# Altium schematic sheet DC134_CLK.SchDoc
size 431 x 279 mm; Date: Not shown in title block; ApprovedBy: Not shown in title block; CheckedBy: Not shown in title block; Author: Not shown in title block; CompanyName: Not shown in title block; Engineer: Not shown in title block; Organization: Not shown in title block; Address1: Not shown in title block; Address2: Not shown in title block; Address3: Not shown in title block; Address4: Not shown in title block; DocumentNumber: 4; Revision: Use project parameter SCH_Rev; SheetNumber: 4; SheetTotal: 9; PageSetup: Record=PageOptions¦CenterHorizontal=True¦CenterVertical=True¦PrintScale=1.00¦XCorrection=1.00¦YCorrection=1.00¦PrintKind=0¦BorderSize=5000000¦LeftOffset=0¦BottomOffset=0¦Orientation=2¦PaperLength=1000¦PaperWidth=1000¦Scale=100¦PaperSource=15¦PrintQuality=600¦MediaType=1¦DitherType=10¦PaperKind=Letter¦PrintScaleMode=1
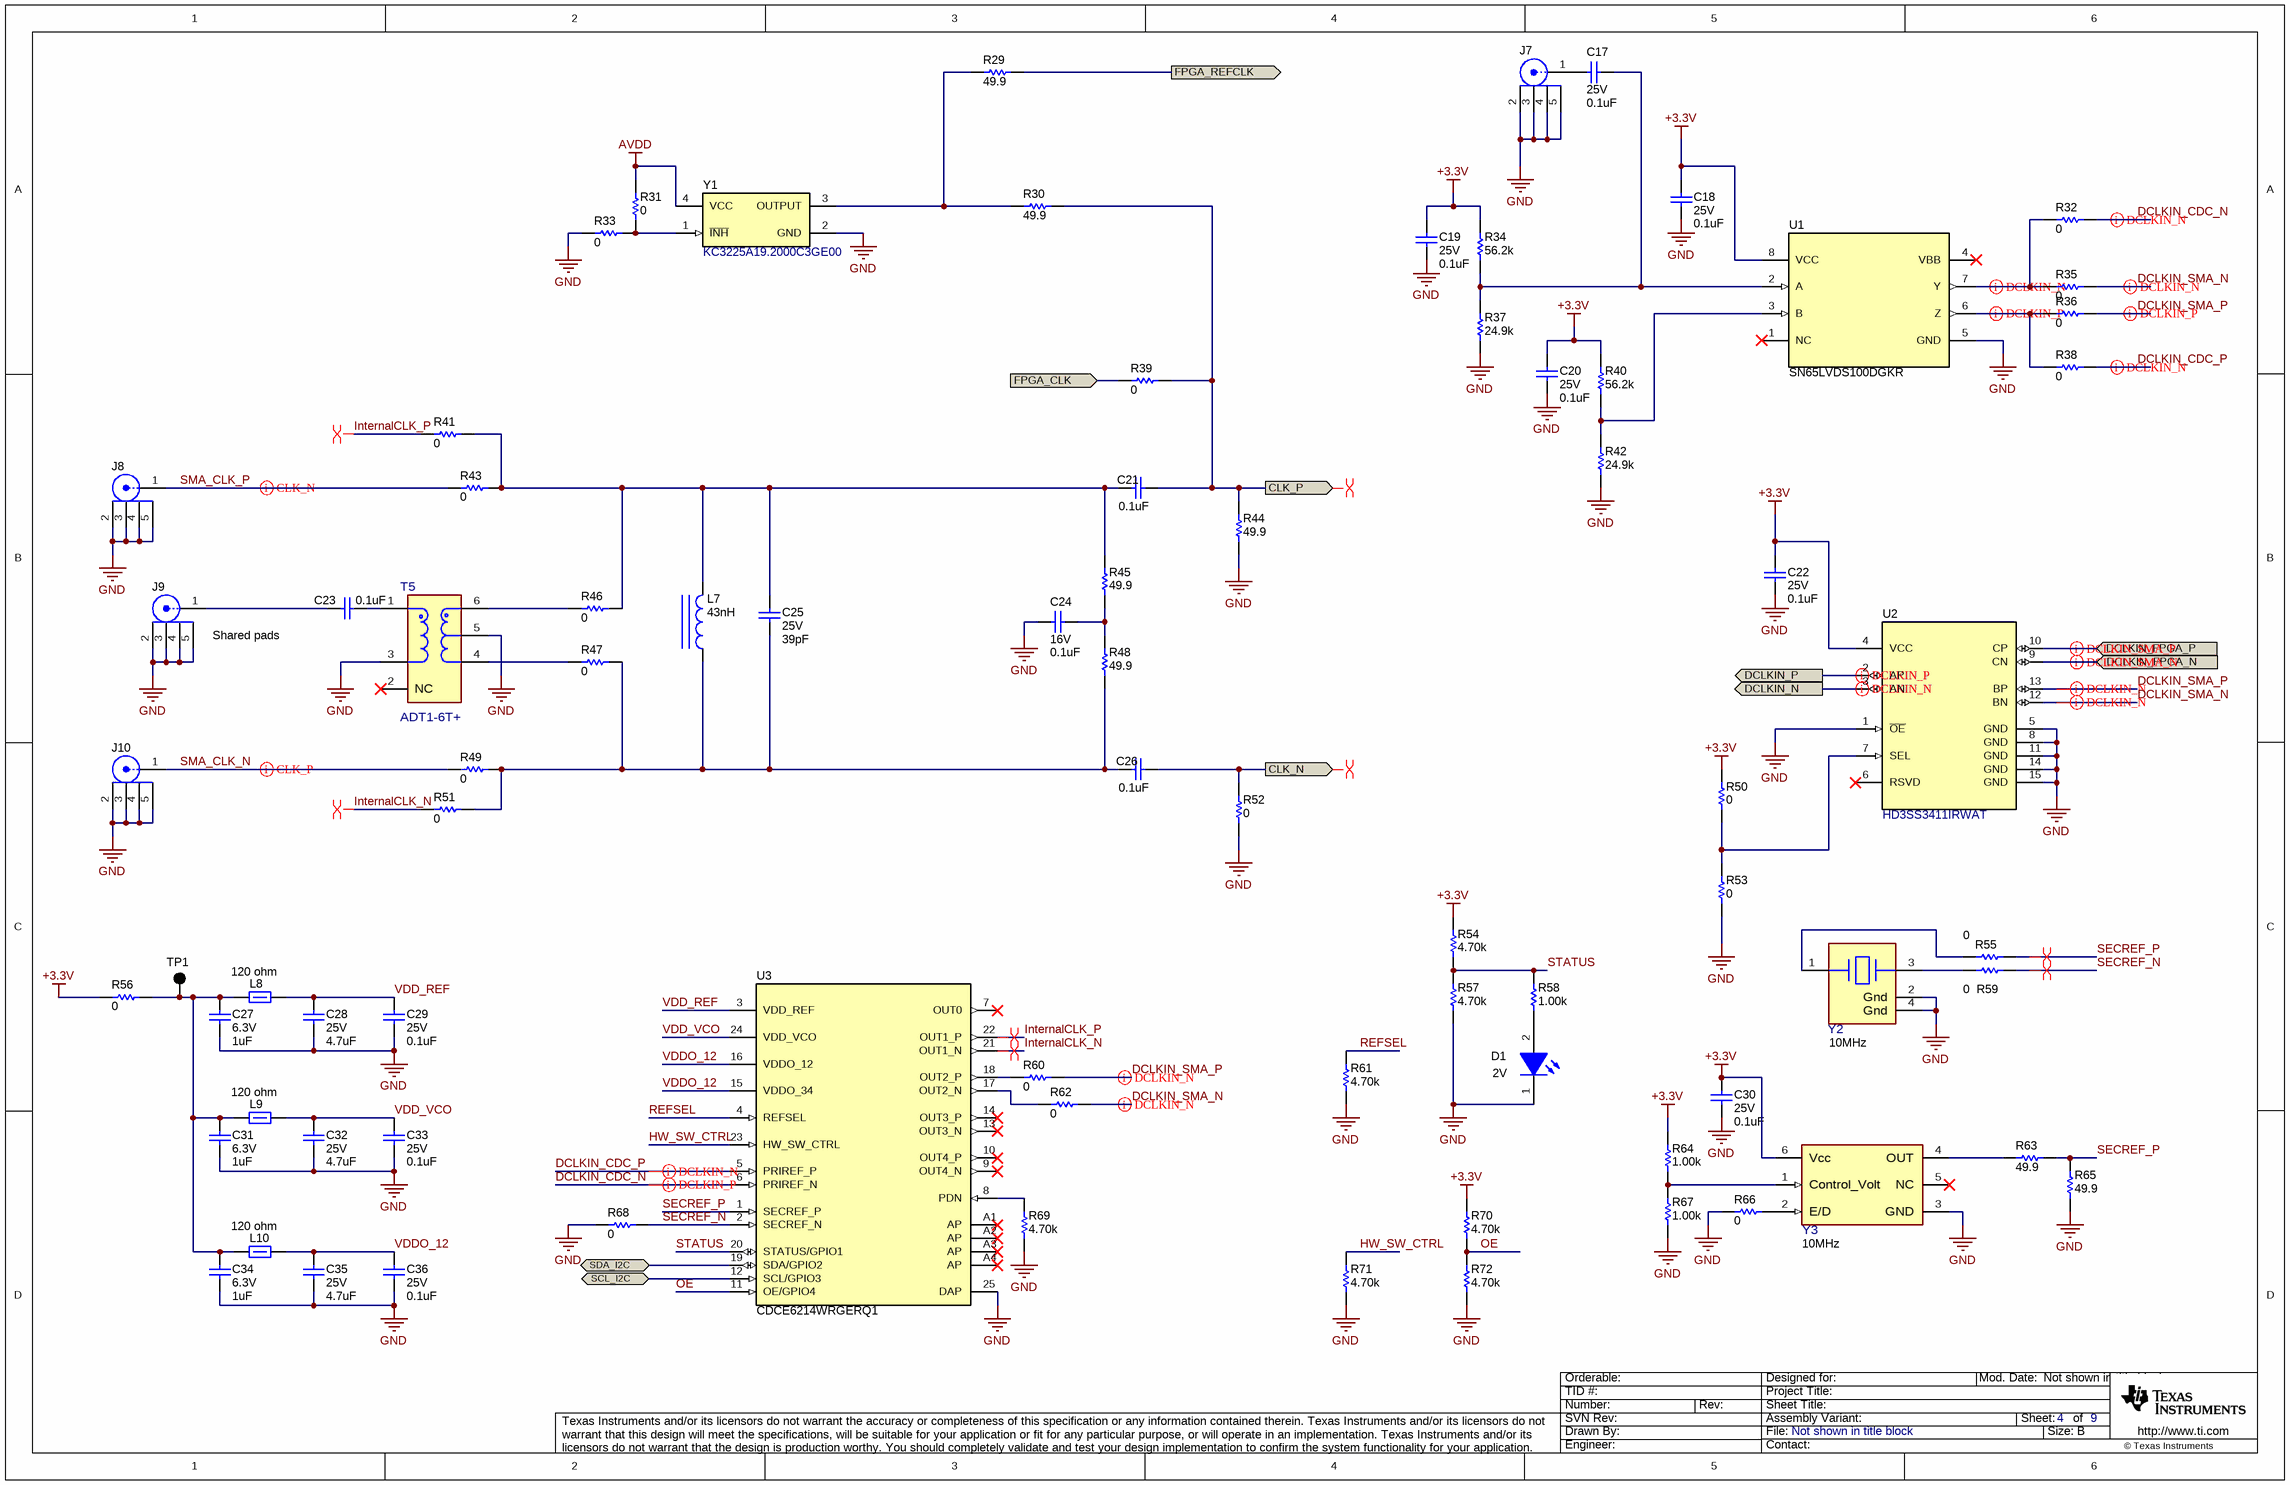
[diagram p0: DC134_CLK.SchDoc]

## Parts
C17  VDC_V: 25V  ValueDisplayed: 0.1uF  [0402]  (hidden comment: GRM155R61E104KA87D)
C18  VDC_V: 25V  ValueDisplayed: 0.1uF  [0402]  (hidden comment: GRM155R61E104KA87D)
C19  VDC_V: 25V  ValueDisplayed: 0.1uF  [0402]  (hidden comment: GRM155R61E104KA87D)
C20  VDC_V: 25V  ValueDisplayed: 0.1uF  [0402]  (hidden comment: GRM155R61E104KA87D)
C21  ValueDisplayed: 0.1uF  [0201L]  (hidden comment: GRM033Z71C104KE14D)
C22  VDC_V: 25V  ValueDisplayed: 0.1uF  [0402]  (hidden comment: GRM155R61E104KA87D)
C23  ValueDisplayed: 0.1uF  [0201L]  (hidden comment: GRM033Z71C104KE14D)
C24  VDC_V: 16V  ValueDisplayed: 0.1uF  [0201L]  (hidden comment: GRM033Z71C104KE14D)
C25  VDC_V: 25V  ValueDisplayed: 39pF  [0402]  (hidden comment: GRM1555C1E390JA01D)
C26  ValueDisplayed: 0.1uF  [0201L]  (hidden comment: GRM033Z71C104KE14D)
C27  VDC_V: 6.3V  ValueDisplayed: 1uF  [0402]  (hidden comment: GRM152R60J105ME15D)
C28  VDC_V: 25V  ValueDisplayed: 4.7uF  [0603]  (hidden comment: GRM188R61E475KE11D)
C29  VDC_V: 25V  ValueDisplayed: 0.1uF  [0201_033]  (hidden comment: GRM033R61E104KE14J)
C30  VDC_V: 25V  ValueDisplayed: 0.1uF  [0201_033]  (hidden comment: GRM033R61E104KE14J)
C31  VDC_V: 6.3V  ValueDisplayed: 1uF  [0402]  (hidden comment: GRM152R60J105ME15D)
C32  VDC_V: 25V  ValueDisplayed: 4.7uF  [0603]  (hidden comment: GRM188R61E475KE11D)
C33  VDC_V: 25V  ValueDisplayed: 0.1uF  [0201_033]  (hidden comment: GRM033R61E104KE14J)
C34  VDC_V: 6.3V  ValueDisplayed: 1uF  [0402]  (hidden comment: GRM152R60J105ME15D)
C35  VDC_V: 25V  ValueDisplayed: 4.7uF  [0603]  (hidden comment: GRM188R61E475KE11D)
C36  VDC_V: 25V  ValueDisplayed: 0.1uF  [0201_033]  (hidden comment: GRM033R61E104KE14J)
D1  Value2: 2V  [LTST-C150_1206_Green]  (hidden comment: LTST-C150KGKT)
J7  901-144-8RFX  [AMPHENOL_901-144-8RFX]  (value not drawn)
J8  142-0701-801  [Johnson_142-0701-801]  (value not drawn)
J9  901-144-8RFX  [AMPHENOL_901-144-8RFX]  (value not drawn)
J10  142-0701-801  [Johnson_142-0701-801]  (value not drawn)
L7  ValueDisplayed: 43nH  [LQG15WZ_02]  (hidden comment: LQG15WZ43NG02D)
L8  value 120 ohm  [0603]  (hidden comment: BLM18KG121TH1D)
L9  value 120 ohm  [0603]  (hidden comment: BLM18KG121TH1D)
L10  value 120 ohm  [0603]  (hidden comment: BLM18KG121TH1D)
R29  ValueDisplayed: 49.9  [0201L]  (hidden comment: RC0201FR-7D49R9L)
R30  ValueDisplayed: 49.9  [0201L]  (hidden comment: RC0201FR-7D49R9L)
R31  ValueDisplayed: 0  [0201L]  (hidden comment: CRCW02010000Z0ED)
R32  ValueDisplayed: 0  [0201L]  (hidden comment: CRCW02010000Z0ED)
R33  ValueDisplayed: 0  [0201L]  (hidden comment: CRCW02010000Z0ED)
R34  ValueDisplayed: 56.2k  [0402]  (hidden comment: CRCW040256K2FKED)
R35  ValueDisplayed: 0  [0201L]  (hidden comment: CRCW02010000Z0ED)
R36  ValueDisplayed: 0  [0201L]  (hidden comment: CRCW02010000Z0ED)
R37  ValueDisplayed: 24.9k  [0402]  (hidden comment: CRCW040224K9FKED)
R38  ValueDisplayed: 0  [0201L]  (hidden comment: CRCW02010000Z0ED)
R39  ValueDisplayed: 0  [0201L]  (hidden comment: CRCW02010000Z0ED)
R40  ValueDisplayed: 56.2k  [0402]  (hidden comment: CRCW040256K2FKED)
R41  ValueDisplayed: 0  [0201L]  (hidden comment: CRCW02010000Z0ED)
R42  ValueDisplayed: 24.9k  [0402]  (hidden comment: CRCW040224K9FKED)
R43  ValueDisplayed: 0  [0201L]  (hidden comment: CRCW02010000Z0ED)
R44  ValueDisplayed: 49.9  [0201L]  (hidden comment: RC0201FR-7D49R9L)
R45  ValueDisplayed: 49.9  [0201L]  (hidden comment: RC0201FR-7D49R9L)
R46  ValueDisplayed: 0  [0201L]  (hidden comment: CRCW02010000Z0ED)
R47  ValueDisplayed: 0  [0201L]  (hidden comment: CRCW02010000Z0ED)
R48  ValueDisplayed: 49.9  [0201L]  (hidden comment: RC0201FR-7D49R9L)
R49  ValueDisplayed: 0  [0201L]  (hidden comment: CRCW02010000Z0ED)
R50  ValueDisplayed: 0  [0201L]  (hidden comment: CRCW02010000Z0ED)
R51  ValueDisplayed: 0  [0201L]  (hidden comment: CRCW02010000Z0ED)
R52  ValueDisplayed: 0  [0201L]  (hidden comment: CRCW02010000Z0ED)
R53  ValueDisplayed: 0  [0201L]  (hidden comment: CRCW02010000Z0ED)
R54  ValueDisplayed: 4.70k  [0201]  (hidden comment: RC0201FR-7D4K7L)
R55  ValueDisplayed: 0  [0201L]  (hidden comment: CRCW02010000Z0ED)
R56  ValueDisplayed: 0  [0603]  (hidden comment: RMCF0603ZT0R00)
R57  ValueDisplayed: 4.70k  [0201]  (hidden comment: RC0201FR-7D4K7L)
R58  ValueDisplayed: 1.00k  [0402]  (hidden comment: RC0402FR-071KL)
R59  ValueDisplayed: 0  [0201L]  (hidden comment: CRCW02010000Z0ED)
R60  ValueDisplayed: 0  [0201L]  (hidden comment: CRCW02010000Z0ED)
R61  ValueDisplayed: 4.70k  [0201]  (hidden comment: RC0201FR-7D4K7L)
R62  ValueDisplayed: 0  [0201L]  (hidden comment: CRCW02010000Z0ED)
R63  ValueDisplayed: 49.9  [0201L]  (hidden comment: RC0201FR-7D49R9L)
R64  ValueDisplayed: 1.00k  [0201L]  (hidden comment: RC0201FR-071KL)
R65  ValueDisplayed: 49.9  [0201L]  (hidden comment: RC0201FR-7D49R9L)
R66  ValueDisplayed: 0  [0201L]  (hidden comment: CRCW02010000Z0ED)
R67  ValueDisplayed: 1.00k  [0201L]  (hidden comment: RC0201FR-071KL)
R68  ValueDisplayed: 0  [0201L]  (hidden comment: CRCW02010000Z0ED)
R69  ValueDisplayed: 4.70k  [0201]  (hidden comment: RC0201FR-7D4K7L)
R70  ValueDisplayed: 4.70k  [0201]  (hidden comment: RC0201FR-7D4K7L)
R71  ValueDisplayed: 4.70k  [0201]  (hidden comment: RC0201FR-7D4K7L)
R72  ValueDisplayed: 4.70k  [0201]  (hidden comment: RC0201FR-7D4K7L)
T5  ADT1-6T+  [FP-ADT1-6T+_SMD6-MFG]  (value not drawn)
TP1  5011  [Keystone5011]  (value not drawn)
U1  SN65LVDS100DGKR  [DGK0008A_L]
U2  HD3SS3411IRWAT  [RWA0014A]
U3  CDCE6214WRGERQ1  [RGE0024P]
Y1  KC3225A19.2000C3GE00  [Kyocera_KC3225A]
Y2  Frequency_Fixed: 10MHz  [FP-ECS-100-12-33-AGN-TR_XTAL_SMD_3MM2_2MM5-MFG]  (hidden comment: ECS-100-12-33-AGN-TR)
Y3  Frequency_Fixed: 10MHz  [FP-CVHD-957-10.000_SMT_XTAL_14MM2_9MM14-MFG]  (hidden comment: CVHD-957-10.000)

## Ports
CLK_N (out), CLK_P (out), DCLKIN_FPGA_N (in), DCLKIN_FPGA_P (in), DCLKIN_N (out), DCLKIN_P (out), FPGA_CLK (in), FPGA_REFCLK (out), SCL_I2C (bidir), SDA_I2C (bidir)

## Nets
+3.3V: C18.2 C19.2 C20.2 C22.2 C30.1 R34.2 R40.2 R50.2 R54.2 R56.1 R64.2 R70.2 U1.8(VCC) U2.4(VCC) Y3.6(Vcc)
AVDD: R31.2 Y1.4(VCC)
GND: C18.1 C19.1 C20.1 C22.1 C24.1 C27.2 C28.2 C29.2 C30.2 C31.2 C32.2 C33.2 C34.2 C35.2 C36.2 D1.1(K) J7.2 J7.3 J7.4 J7.5 J8.2 J8.3 J8.4 J8.5 J9.2 J9.3 J9.4 J9.5 J10.2 J10.3 J10.4 J10.5 R33.1 R37.1 R42.1 R44.1 R52.1 R53.1 R57.1 R61.1 R65.1 R66.2 R67.1 R68.2 R69.1 R71.1 R72.1 T5.3 T5.5 U1.5(GND) U2.1(~{OE}) U2.5(GND) U2.8(GND) U2.11(GND) U2.14(GND) U2.15(GND) U3.25(DAP) Y1.2(GND) Y2.2(Gnd) Y2.4(Gnd) Y3.3(GND)
CLK_N: C26.2 R52.2 ; port CLK_N
CLK_P: C21.2 R30.2 R39.2 R44.2 ; port CLK_P
DCLKIN_CDC_N: R32.2 U3.6(PRIREF_N)
DCLKIN_CDC_P: R38.2 U3.5(PRIREF_P)
DCLKIN_FPGA_N: U2.9(CN) ; port DCLKIN_FPGA_N
DCLKIN_FPGA_P: U2.10(CP) ; port DCLKIN_FPGA_P
DCLKIN_N: U2.3(AN) ; port DCLKIN_N
DCLKIN_P: U2.2(AP) ; port DCLKIN_P
DCLKIN_SMA_N: R35.2 R62.2 U2.12(BN)
DCLKIN_SMA_P: R36.2 R60.2 U2.13(BP)
FPGA_CLK: R39.1 ; port FPGA_CLK
FPGA_REFCLK: R29.2 ; port FPGA_REFCLK
HW_SW_CTRL: R71.2 U3.23(HW_SW_CTRL)
InternalCLK_N: R51.1 U3.21(OUT1_N)
InternalCLK_P: R41.1 U3.22(OUT1_P)
OE: R70.1 R72.2 U3.11(OE/GPIO4)
REFSEL: R61.2 U3.4(REFSEL)
SCL_I2C: U3.12(SCL/GPIO3) ; port SCL_I2C
SDA_I2C: U3.19(SDA/GPIO2) ; port SDA_I2C
SECREF_N: R59.1 R68.1 U3.2(SECREF_N)
SECREF_P: R55.1 R63.2 R65.2 U3.1(SECREF_P)
SMA_CLK_N: J10.1 R49.1
SMA_CLK_P: J8.1 R43.1
STATUS: R54.1 R57.2 R58.2 U3.20(STATUS/GPIO1)
VDD_REF: C28.1 C29.1 L8.2 U3.3(VDD_REF)
VDD_VCO: C32.1 C33.1 L9.2 U3.24(VDD_VCO)
VDDO_12: C35.1 C36.1 L10.2 U3.15(VDDO_34) U3.16(VDDO_12)
NetC17_1: C17.1 R34.1 R37.2 U1.2(A)
NetC17_2: C17.2 J7.1
NetC21_1: C21.1 C25.1 L7.2 R41.2 R43.2 R45.1 R46.2
NetC23_1: C23.1 J9.1
NetC23_2: C23.2 T5.1
NetC24_2: C24.2 R45.2 R48.1
NetC25_2: C25.2 C26.1 L7.1 R47.2 R48.2 R49.2 R51.2
NetC27_1: C27.1 C31.1 C34.1 L8.1 L9.1 L10.1 R56.2 TP1.1
NetD1_2: D1.2(A) R58.1
NetR29_1: R29.1 R30.1 Y1.3(OUTPUT)
NetR31_1: R31.1 R33.2 Y1.1(~{INH})
NetR32_1: R32.1 R35.1 U1.7(Y)
NetR36_1: R36.1 R38.1 U1.6(Z)
NetR40_1: R40.1 R42.2 U1.3(B)
NetR46_1: R46.1 T5.6
NetR47_1: R47.1 T5.4
NetR50_1: R50.1 R53.2 U2.7(SEL)
NetR55_2: R55.2 Y2.1(In/Out)
NetR59_2: R59.2 Y2.3(Out/In)
NetR60_1: R60.1 U3.18(OUT2_P)
NetR62_1: R62.1 U3.17(OUT2_N)
NetR63_1: R63.1 Y3.4(OUT)
NetR64_1: R64.1 R67.2 Y3.1(Control_Volt)
NetR66_1: R66.1 Y3.2(E/D)
NetR69_2: R69.2 U3.8(PDN)

Not connected (* = marked no-connect by the designer): T5 2(NC)*; U1 1(NC)* 4(VBB)*; U2 6(RSVD)*; U3 7(OUT0)* 9(OUT4_N)* 10(OUT4_P)* 13(OUT3_N)* 14(OUT3_P)* A1(AP)* A2(AP)* A3(AP)* A4(AP)*; Y3 5(NC)*

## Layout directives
differential pair: CLK_N, CLK_P, DCLKIN_CDC_N, DCLKIN_CDC_P, DCLKIN_FPGA_N, DCLKIN_FPGA_P, DCLKIN_N, DCLKIN_P, DCLKIN_SMA_N, DCLKIN_SMA_P, InternalCLK_N, InternalCLK_P, NetR32_1, NetR36_1, SECREF_N, SECREF_P, SMA_CLK_N, SMA_CLK_P

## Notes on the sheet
- (near J9) Shared pads

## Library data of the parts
C17-C20 C22 = CMP-0006607-2: CAP, CERM, 0.1 uF, 25 V, +/- 10%, X5R, 0402; Manufacturer: MuRata; TaMin_C: -55°C; Polarized: N; SizeAreaWB_mm2: 3; Value1: Unknown; U/M: EA; Value: 0.1uF; TaMax_C: 85°C; SizeZ_mm: 0.6; SizeX_mm: 1; SizeY_mm: 0.5; Cap_F: 100nF; AEC Category: Q200
C21 C23 C26 = CMP-0064970-1: CAP, CERM, 0.1 uF, 16 V,+/- 10%, X7R, 0201; Manufacturer: MuRata; TaMin_C: -55°C; Polarized: N; SizeAreaWB_mm2: 2.08; Value1: Unknown; U/M: EA; Value: 0.1uF; TaMax_C: 125°C; SizeZ_mm: 0.26; SizeX_mm: 0.6; SizeY_mm: 0.3; Cap_Case: 0201; Value2: 16V; SizeArea_mm2: 0.18; CompType: Capacitor; Cap_F: 100nF; AEC Category: Q200
C24 = CMP-0064970-1: CAP, CERM, 0.1 uF, 16 V,+/- 10%, X7R, 0201; Manufacturer: MuRata; TaMin_C: -55°C; Polarized: N; SizeAreaWB_mm2: 2.08; Value1: Unknown; U/M: EA; Value: 0.1uF; TaMax_C: 125°C; SizeZ_mm: 0.26; SizeX_mm: 0.6; SizeY_mm: 0.3; Cap_Case: 0201; SizeArea_mm2: 0.18; CompType: Capacitor; Cap_F: 100nF; AEC Category: Q200
C25 = CMP-0006380-2: CAP, CERM, 39 pF, 25 V, +/- 5%, C0G/NP0, 0402; Manufacturer: MuRata; TaMin_C: -55°C; Polarized: N; SizeAreaWB_mm2: 3; Value1: Unknown; U/M: EA; Value: 39pF; TaMax_C: 125°C; SizeZ_mm: 0.6; SizeX_mm: 1; SizeY_mm: 0.5; AEC Category: Q200
C27 C31 C34 = CMP-0006372-2: CAP, CERM, 1 uF, 6.3 V, +/- 20%, X5R, 0402; Manufacturer: MuRata; TaMin_C: -55°C; Polarized: N; SizeAreaWB_mm2: 3; Value1: Unknown; U/M: EA; Value: 1uF; TaMax_C: 85°C; SizeZ_mm: 0.6; SizeX_mm: 1; SizeY_mm: 0.5; Cap_F: 1µF; AEC Category: Q200
C28 C32 C35 = CMP-0007347-5: CAP, CERM, 4.7 uF, 25 V, +/- 10%, X5R, 0603; Manufacturer: MuRata; TaMin_C: -55°C; Polarized: N; SizeAreaWB_mm2: 4.68; Value1: Unknown; U/M: EA; Value: 4.7uF; TaMax_C: 85°C; SizeZ_mm: 1; SizeX_mm: 1.6; SizeY_mm: 0.8; SizeArea_mm2: 1.28; Cap_F: 4.7µF; AEC Category: Q200
C29 C30 C33 C36 = CMP-0009719-2: CAP, CERM, 0.1 uF, 25 V, +/- 10%, X5R, 0201; Manufacturer: MuRata; TaMin_C: -55°C; Polarized: N; SizeAreaWB_mm2: 2.08; Value1: Unknown; U/M: EA; Value: 0.1uF; TaMax_C: 85°C; SizeZ_mm: 0.33; SizeX_mm: 0.6; SizeY_mm: 0.3; Cap_Case: 0201; SizeArea_mm2: 0.18; Cap_F: 100nF; AEC Category: Q200
D1 = CMP-0002920-2: LED, Green, SMD; Manufacturer: LiteOn; Io_A: 30mA; Vr_V: 5V; Tjmax_C: 85°C; Value1: W; Angle: 130; Type: AlInGaP
J7 J9 = CMP-0055833-1: SMA Straight Jack, Gold, 50 Ohm, TH; Manufacturer: Amphenol RF; CNHeader: FALSE; Green_Lifecycle: Not Set; Green_REACh: Incomplete; CT: TRUE
J8 J10 = CMP-0055828-1: Connector, End launch SMA, 50 ohm, SMT; Manufacturer: Cinch Connectivity; CNHeader: FALSE; Green_Lifecycle: Not Set; Green_REACh: Incomplete; CT: TRUE
L7 = CMP-0080278-3: Inductor, Multilayer, Air Core, 43 nH, 0.19 A, 1.6 ohm, AEC-Q200 Grade 1, SMD; Manufacturer: MuRata; Irms: 0.19A @ 25C rise; SizeAreaWB_mm2: 3.2; DCR_ohm: 1.6; Value1: 1.6 ohm; Value: 43nH; Imax_A: 190mA; SizeZ_mm: 0.6; SizeX_mm: 1; Value2: 0.19A; AEC Qualified: Y; AEC Category: Q200
L8-L10 = CMP-0077879-2: Ferrite Bead, 120 ohm @ 100 MHz, 1.9 A, 0603; Manufacturer: MuRata; ZTyp@100MHz_Ohm: 120; SizeAreaWB_mm2: 4.68; DCR_ohm: 0.04; Value1: 0.04 ohm; Imax_A: 1.9A; SizeZ_mm: 1.0; SizeX_mm: 1.6; SizeY_mm: 0.8; SizeArea_mm2: 1.28
R29 R30 R45 R48 R63 R65 = CMP-0028028-1: RES, 49.9, 1%, 0.05 W, 0201; Manufacturer: Yageo America; Power_W: 50mW; TempCo: 200 ppm/C; Value_Code: 49R9; U/M: EA; Value: 49.9; EIA_Code: E96; SizeX_mm: 0.6; SizeY_mm: 0.3; SizeZ_mm: 0.26; Value2: 0.05W; SizeArea_mm2: 0.18; CompType: Resistor; AEC Qualified: N; VDC_V: 25V; AEC Category: Q200
R31-R33 R35 R36 R38 R39 R41 R43 R46 R47 R49-R53 R55 R59 R60 R62 R66 R68 = CMP-0027008-4: RES, 0, 5%, 0.05 W, 0201; Manufacturer: Vishay-Dale; Power_W: 50mW; TempCo: ppm/C; Value_Code: 0000; Value: 0; EIA_Code: E24; SizeX_mm: 0.6; SizeY_mm: 0.3; SizeZ_mm: 0.26; Value2: 0.05W; SizeArea_mm2: 0.18; AEC Qualified: N; AEC Category: Q200
R34 R40 = CMP-0026453-2: RES, 56.2 k, 1%, 0.063 W, AEC-Q200 Grade 0, 0402; Manufacturer: Vishay-Dale; Power_W: 63mW; TempCo: 100 ppm/C; Value_Code: 56k2; Value: 56.2k; EIA_Code: E96; SizeX_mm: 1; SizeY_mm: 0.5; SizeZ_mm: 0.6; Value2: 0.063W; AEC Qualified: Y; VDC_V: 50V; AEC Category: Q200; AEC Grade: 0
R37 R42 = CMP-0026196-2: RES, 24.9 k, 1%, 0.063 W, AEC-Q200 Grade 0, 0402; Manufacturer: Vishay-Dale; Power_W: 63mW; TempCo: 100 ppm/C; Value_Code: 24k9; Value: 24.9k; EIA_Code: E96; SizeX_mm: 1; SizeY_mm: 0.5; SizeZ_mm: 0.6; Value2: 0.063W; AEC Qualified: Y; VDC_V: 50V; AEC Category: Q200; AEC Grade: 0
R44 = CMP-0028028-1: RES, 49.9, 1%, 0.05 W, 0201; Manufacturer: Yageo America; Power_W: 50mW; TempCo: 200 ppm/C; Value_Code: 49R9; U/M: EA; Value: 49.9; EIA_Code: E96; SizeX_mm: 0.6; SizeY_mm: 0.3; SizeZ_mm: 0.26; Value2: 0.05W; SizeArea_mm2: 0.18; AEC Qualified: N; VDC_V: 25V; AEC Category: Q200
R54 R57 R61 R69-R72 = CMP-0028031-1: RES, 4.70 k, 1%, 0.05 W, 0201; Manufacturer: Yageo America; Power_W: 50mW; TempCo: 200 ppm/C; Value_Code: 4k70; U/M: EA; Value: 4.70k; Res_ohm: 4.7k; SizeX_mm: 0.6; SizeY_mm: 0.3; SizeZ_mm: 0.26; Value2: 0.05W; SizeArea_mm2: 0.18; AEC Qualified: N; VDC_V: 25V; AEC Category: Q200
R56 = CMP-0023343-3: RES, 0, 1%, 0.1 W, AEC-Q200 Grade 0, 0603; Manufacturer: Stackpole Electronics Inc; Power_W: 100mW; TempCo: ppm/C; U/M: EA; Value: 0; SizeX_mm: 1.6; SizeY_mm: 0.8; SizeZ_mm: 1; Value2: 0.1W; SizeArea_mm2: 1.28; AEC Qualified: Y; AEC Category: Q200
R58 = CMP-0026725-1: RES, 1.00 k, 1%, 0.0625 W, 0402; Manufacturer: Yageo America; Power_W: 62.5mW; TempCo: 100 ppm/C; Value_Code: 1k00; U/M: EA; Value: 1.00k; EIA_Code: E96; Res_ohm: 1k; SizeX_mm: 1; SizeY_mm: 0.5; SizeZ_mm: 0.6; AEC Qualified: N; VDC_V: 50V; AEC Category: Q200
R64 R67 = CMP-0027453-1: RES, 1.00 k, 1%, 0.05 W, 0201; Manufacturer: Yageo America; Power_W: 50mW; TempCo: 200 ppm/C; Value_Code: 1k00; U/M: EA; Value: 1.00k; EIA_Code: E96; Res_ohm: 1k; SizeX_mm: 0.6; SizeY_mm: 0.3; SizeZ_mm: 0.26; Value2: 0.05W; SizeArea_mm2: 0.18; AEC Qualified: N; VDC_V: 25V; AEC Category: Q200
T5 = CMP-0086669-1: Transformer 50Ω/0.03 to 125 MHz; Manufacturer: Mini-Circuits; Rsec1_ohm: 50; Ns1toNp: 1:1; SizeZ_mm: .206inch; AEC Qualified: No
TP1 = CMP-0055148-1: Test Point, Multipurpose, Black, TH; Manufacturer: Keystone; CNHeader: FALSE; Green_Lifecycle: Active; Green_REACh: Passed; ContactFinish: Silver; CT: TRUE
U1 = CMP-0076021-2: 2 Gbps LVDS/LVPECL/CML to LVDS Buffer/Repeater/Translator, DGK0008A (VSSOP-8); Manufacturer: Texas Instruments; SizeAreaWB_mm2: 23.6; SizeArea_mm2: 14.7; SizeZ_mm: 1.1; SizeY_mm: 3; CompType: IC; SizeX_mm: 4.9; AEC Category: Q200; AEC Qualified: N
U2 = CMP-0074453-1: One Channel Differential 2:1 Mux/Demux, RWA0014A (WQFN-14); Alternate Manufacturer: Texas Instruments; SizeAreaWB_mm2: 20.25; U/M: EA; SizeZ_mm: 0.8; SizeX_mm: 3.5; SizeArea_mm2: 12.25; CompType: IC
U3 = CMP-0750065-2: CDCE6214WRGERQ1, RGE0024P (VQFN-24); Alternate PartNumber: CDCE6214WRGETQ1; Alternate Manufacturer: Texas Instruments; AEC Qualified: Y; SizeArea_mm2: 16; SizeAreaWB_mm2: 25; SizeX_mm: 4; CompType: IC; AEC Category: Q200; SizeZ_mm: 0.9
Y1 = CMP-0006126-3: Clock Oscillator, 19.2 MHz, CMOS, 3.3V, SMD; Manufacturer: Kyocera; TaMin_C: -40°C; Frequency Stability: +/-50ppm; SizeAreaWB_mm2: 14.7; TaMax_C: 85°C; SizeZ_mm: 1; SizeX_mm: 2.5; SizeY_mm: 3.2; SizeArea_mm2: 8
Y2 = CMP-0090315-1: Crystal 10MHz ±25ppm (Tol) ±30ppm (Stability) 12pF FUND 100Ohm 4-Pin Mini-CSMD T/R; Manufacturer: ECS; Esr: 100; AEC Qualified: No; SizeZ_mm: 0.8mm
Y3 = CMP-0088179-1: Ultra-low Phase Noise VCXO with Standby Mode; Manufacturer: Crystek Corporation; Load Capacitance: 15pF; AEC Qualified: No; SizeZ_mm: 5.3mm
